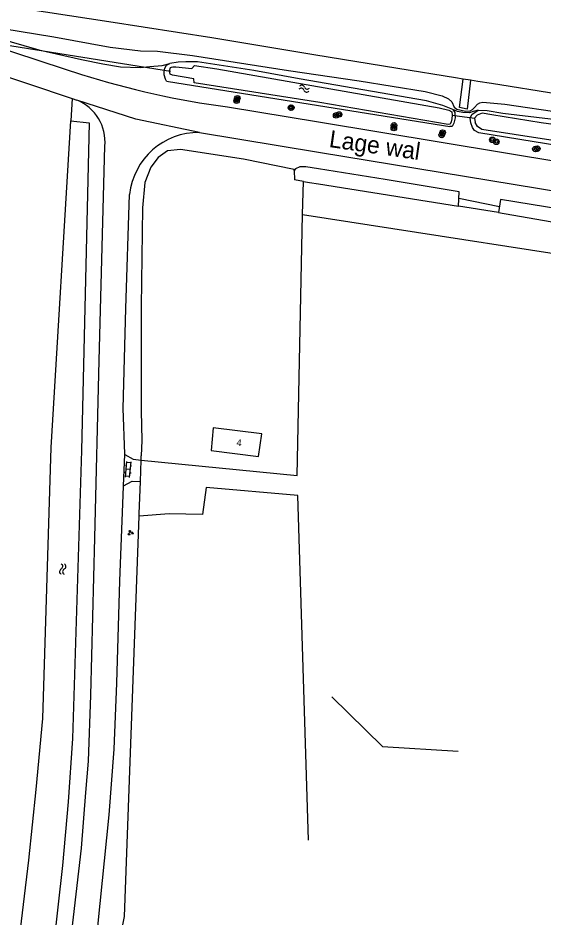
# Model space of a CAD drawing. Extents: x 132994 to 136000, y 393499 to 395512.
# Drawn here: x 133956 to 134032.8, y 394004.5 to 394136.1 of the extents above; entities that cross this region are included whole.
import ezdxf

# ---------------------------------------------------------------- set-up
doc = ezdxf.new("R2010")
doc.units = 0
for name, color, linetype in [('gg-afsc-erfafscheiding', 7, 'Continuous'), ('gg-afsc-hekwerk', 7, 'Continuous'), ('gg-afsc-lijn draadraster', 7, 'Continuous'), ('gg-anno-huisnummerreeks BGT', 7, 'Continuous'), ('gg-anno-openbare ruimte label', 7, 'Continuous'), ('gg-bbg-hoofdgebouw', 7, 'Continuous'), ('gg-knt-BGT kruinlijn', 7, 'Continuous'), ('gg-knt-verharding', 7, 'Continuous'), ('gg-kntw-bovenkant insteek waterloop', 7, 'Continuous'), ('gg-kwrk-duiker nz buis', 7, 'Continuous'), ('gt-grn-groengrens', 7, 'Continuous'), ('gt-grn-vlakafsluiter', 7, 'Continuous'), ('gt-grn-weggrens', 7, 'Continuous'), ('gt-symb-boom', 7, 'Continuous'), ('gt-symb-groenvak', 7, 'Continuous'), ('gt-symb-klinker verharding', 7, 'Continuous'), ('gt-symb-watersymbool', 7, 'Continuous'), ('gx-grn-maaiveld', 7, 'Continuous')]:
    doc.layers.add(name, color=color, linetype=linetype)

# ---------------------------------------------------------------- blocks, each defined once
blk = doc.blocks.new('gt0-BOOM')
at = {"layer": 'gt-symb-boom'}
for radius in [0.4, 0.2]:
    blk.add_circle((0, 0), radius, dxfattribs=at)
blk = doc.blocks.new('gt0-WA')
at = {"layer": 'gt-symb-watersymbool'}
for centre, start, end in [((-0.32, 0.02), 28.0725, 151.9275), ((0.43, 0.42), 208.0725, 331.9275), ((-0.32, -0.43), 28.0725, 151.9275), ((0.43, -0.03), 208.0725, 331.9275)]:
    blk.add_arc(centre, 0.425, start, end, dxfattribs=at)
blk = doc.blocks.new('gt0-GRVAK')
at = {"layer": 'gt-symb-groenvak'}
for p, q in [((-0.11, 0.19), (-0.23, 0.24)), ((-0.18, 0.15), (0.09, 0.15)), ((-0.09, 0.21), (-0.16, 0.32)), ((-0.05, 0.21), (-0.05, 0.39)), ((0, 0.21), (0.06, 0.32)), ((0.01, 0.19), (0.13, 0.24)), ((0.26, -0.05), (0.2, 0.06)), ((0.3, -0.05), (0.3, 0.13)), ((0.35, -0.05), (0.41, 0.06)), ((-0.25, -0.23), (-0.36, -0.18)), ((-0.32, -0.26), (-0.05, -0.26)), ((-0.23, -0.21), (-0.29, -0.1)), ((-0.18, -0.2), (-0.18, -0.02)), ((-0.14, -0.21), (-0.07, -0.1)), ((-0.12, -0.23), (0, -0.18)), ((0.24, -0.07), (0.12, -0.02)), ((0.17, -0.11), (0.44, -0.11)), ((0.37, -0.07), (0.49, -0.02))]:
    blk.add_line(p, q, dxfattribs=at)
blk = doc.blocks.new('gt0-KL1')
at = {"layer": 'gt-symb-klinker verharding'}
for p, q in [((-1.15, 0.3), (1.15, 0.3)), ((-1, -0.3), (-1, 0.3)), ((-0.5, 0.3), (-0.5, 0.45)), ((0, -0.3), (0, 0.3)), ((0.5, 0.3), (0.5, 0.45)), ((1, -0.3), (1, 0.3)), ((-1.15, -0.3), (1.15, -0.3)), ((-0.5, -0.45), (-0.5, -0.3)), ((0.5, -0.45), (0.5, -0.3))]:
    blk.add_line(p, q, dxfattribs=at)

msp = doc.modelspace()

# ---------------------------------------------------------------- linework, layer by layer
at = {"layer": 'gg-afsc-erfafscheiding'}
msp.add_lwpolyline([(133996.44, 394113.81), (133996.44, 394113.96), (133989.01, 394115.45), (133979.8, 394116.87), (133977.88, 394116.7), (133976.53, 394115.71), (133975.45, 394114.28), (133974.6, 394112.07), (133974.24, 394108.35), (133974.06, 394093.94), (133974.05, 394078.67), (133974.13, 394074.31), (133974.06, 394072.08)], dxfattribs=at)
at = {"layer": 'gg-afsc-hekwerk'}
for p, q in [((133973.93, 394068.34), (133974.04, 394071.45)), ((133973.93, 394068.34), (133974.04, 394071.45)), ((133974.04, 394071.45), (133974.06, 394072.08)), ((133974.04, 394071.45), (133974.06, 394072.08)), ((133973.75, 394063.61), (133973.93, 394068.34)), ((133973.75, 394063.61), (133973.93, 394068.34)), ((133973.74, 394063.27), (133973.75, 394063.61)), ((133973.74, 394063.27), (133973.75, 394063.61))]:
    msp.add_line(p, q, dxfattribs=at)
msp.add_lwpolyline([(133970.67, 394000), (133971.62, 394004.71), (133973.74, 394063.27)], dxfattribs=at)
msp.add_lwpolyline([(133970.67, 394000), (133971.62, 394004.71), (133973.74, 394063.27)], dxfattribs=at)
at = {"layer": 'gg-afsc-lijn draadraster'}
for points in [[(133998.53, 394015.87), (133996.94, 394066.28), (133983.57, 394067.44), (133983.03, 394063.53), (133978.15, 394063.63), (133973.74, 394063.27)], [(134001.91, 394036.83), (134009.32, 394029.61), (134020.42, 394028.9)]]:
    msp.add_lwpolyline(points, dxfattribs=at)
at = {"layer": 'gg-bbg-hoofdgebouw'}
msp.add_lwpolyline([(133991.23, 394072), (133991.71, 394075.32), (133984.56, 394076.16), (133984.26, 394072.87), (133991.23, 394072)], dxfattribs=at)
at = {"layer": 'gg-knt-BGT kruinlijn'}
for p, q in [((133953.82, 394134.59), (133961.29, 394133.35)), ((133961.29, 394133.35), (133969.5, 394131.82)), ((133969.5, 394131.82), (133973.95, 394131.29)), ((133973.95, 394131.29), (133976.45, 394131.24)), ((133976.45, 394131.24), (133981.56, 394130.6)), ((133981.56, 394130.6), (133995.6, 394128.41)), ((133995.6, 394128.41), (134005.95, 394126.92)), ((134005.95, 394126.92), (134015.6, 394125.38)), ((134015.6, 394125.38), (134018.07, 394124.72)), ((134018.07, 394124.72), (134018.99, 394124.28)), ((134018.99, 394124.28), (134019.49, 394123.83)), ((134019.49, 394123.83), (134019.84, 394123.09)), ((134019.84, 394123.09), (134020.2, 394122.75)), ((134020.2, 394122.75), (134021.49, 394122.48)), ((134021.49, 394122.48), (134022.16, 394122.54)), ((134022.16, 394122.54), (134022.52, 394122.73)), ((134022.52, 394122.73), (134022.78, 394123)), ((134022.78, 394123), (134023.23, 394123.51)), ((134023.23, 394123.51), (134023.56, 394123.72)), ((134023.56, 394123.72), (134024.02, 394123.8)), ((134024.02, 394123.8), (134027.26, 394123.5)), ((134027.26, 394123.5), (134042.32, 394121.27))]:
    msp.add_line(p, q, dxfattribs=at)
at = {"layer": 'gg-knt-verharding'}
for p, q in [((133962.78, 394128.68), (133965.34, 394127.85)), ((133963.95, 394124.32), (133964.62, 394124.09)), ((133986.65, 394123.12), (134000, 394120.91)), ((133982.6, 394119.37), (134000, 394116.5)), ((134000, 394116.5), (134157.93, 394090.51)), ((133971.45, 394067.72), (133971.64, 394072.3))]:
    msp.add_line(p, q, dxfattribs=at)
for points in [[(133942.63, 394135.11), (133944.19, 394134.74), (133962.78, 394128.68)], [(133944.04, 394130.94), (133944.46, 394130.85), (133963.95, 394124.32)], [(133960.05, 393973.71), (133961.31, 393982.52), (133963.39, 393997.93), (133965.3, 394014.74), (133965.97, 394022.84), (133966.32, 394027.44), (133966.7, 394037.1), (133967.28, 394060.1), (133967.92, 394086.05), (133968.72, 394117.35)], [(133971.64, 394072.3), (133971.64, 394072.36), (133971.43, 394079.02), (133971.8, 394093.64), (133972.33, 394110.3)], [(133971.64, 394072.3), (133972.87, 394071.6), (133974.04, 394071.45)], [(133963.79, 393973.39), (133965.22, 393983.85), (133967.5, 394001.54), (133967.7, 394003.25), (133969.38, 394019.62), (133970.1, 394029.19), (133970.48, 394038.84), (133970.93, 394053.83), (133971.44, 394067.62), (133971.45, 394067.72)], [(133971.45, 394067.72), (133972.71, 394068.38), (133973.93, 394068.34)]]:
    msp.add_lwpolyline(points, dxfattribs=at)
for centre, radius, start, end in [((134002.41, 394244.59), 122.48, 252.3818, 262.6107), ((133962.23, 394118.02), 6.53, 354.1109, 68.5632), ((133982.47, 394109.17), 10.2, 89.2753, 173.6459)]:
    msp.add_arc(centre, radius, start, end, dxfattribs=at)
at = {"layer": 'gg-kntw-bovenkant insteek waterloop'}
for p, q in [((133977.76, 394126.86), (134000, 394123.3)), ((134000, 394123.3), (134019.19, 394120.22)), ((134019.64, 394122.72), (134018.16, 394123.32)), ((133996.44, 394113.81), (133996.45, 394112.42)), ((133998.69, 394112.07), (134000, 394111.86)), ((134000, 394111.86), (134020.44, 394108.6))]:
    msp.add_line(p, q, dxfattribs=at)
for points in [[(133997.15, 394127.22), (133990.51, 394128.42), (133982.28, 394129.69), (133980.6, 394129.69), (133979.47, 394129.65), (133978.23, 394129.46)], [(134018.16, 394123.32), (134015.79, 394124.01), (133997.15, 394127.22)], [(133956.05, 394000), (133957.62, 394012.97), (133958.68, 394023.31), (133959.65, 394033.66), (133960.9, 394073.32), (133963.77, 394121.07)], [(133963.77, 394121.07), (133966.45, 394120.78), (133965.34, 394072.87), (133964, 394030.76), (133963.35, 394021.48), (133962.52, 394012.2), (133961.18, 394000)], [(134000, 394114.05), (133998.15, 394114.32), (133997.26, 394114.34), (133996.63, 394114.06), (133996.44, 394113.81)], [(134020.44, 394108.6), (134020.55, 394110.69), (134009.75, 394112.49), (134000, 394114.05)], [(134057.36, 394102.28), (134057.19, 394104.13), (134056.78, 394104.46), (134055.93, 394104.77), (134026.59, 394109.59), (134026.32, 394107.65)], [(134026.32, 394107.65), (134051.54, 394103.27), (134054.74, 394102.88), (134054.66, 394101.57)]]:
    msp.add_lwpolyline(points, dxfattribs=at)
at = {"layer": 'gg-kwrk-duiker nz buis'}
for p, q in [((134019.54, 394121.91), (134022.82, 394121.45)), ((134020.5, 394109.74), (134026.44, 394108.52))]:
    msp.add_line(p, q, dxfattribs=at)
msp.add_lwpolyline([(133897.87, 394141.41), (133938.59, 394134.68), (133978.32, 394128.35)], dxfattribs=at)
at = {"layer": 'gt-grn-groengrens'}
msp.add_line((133963.95, 394124.32), (133963.77, 394121.07), dxfattribs=at)
at = {"layer": 'gt-grn-vlakafsluiter'}
msp.add_line((134026.32, 394107.65), (134020.44, 394108.6), dxfattribs=at)
at = {"layer": 'gt-grn-weggrens'}
msp.add_lwpolyline([(133982.6, 394119.37), (133973.24, 394121.3), (133964.62, 394124.09)], dxfattribs=at)
at = {"layer": 'gx-grn-maaiveld'}
for p, q in [((134022.24, 394127), (134021.14, 394127.18)), ((134023.36, 394122.65), (134022.6, 394122.43)), ((134000, 394120.91), (134158.62, 394094.62)), ((133997.77, 394112.21), (133996.45, 394112.42)), ((133997.64, 394107.35), (133997.77, 394112.21)), ((133997.77, 394112.21), (133998.69, 394112.07))]:
    msp.add_line(p, q, dxfattribs=at)
for points in [[(134021.14, 394127.18), (134020.04, 394127.35), (134011.61, 394128.7), (133999.3, 394130.71), (133984.38, 394133.18), (133969.33, 394135.55), (133954.31, 394137.81), (133943.34, 394139.62), (133934.23, 394141.04)], [(133943.32, 394135.82), (133947.79, 394134.64), (133952.79, 394133.26), (133959.08, 394131.45), (133965.3, 394130.05), (133968.45, 394129.4), (133971.02, 394128.97), (133973.88, 394128.89), (133975.31, 394129.02), (133977.13, 394129.14), (133978.23, 394129.46)], [(133977.76, 394126.86), (133977.59, 394127.17), (133977.43, 394127.8), (133977.43, 394128.25), (133977.52, 394128.78), (133977.75, 394129.21), (133978.23, 394129.46)], [(133978.17, 394128.39), (133978.35, 394128.86), (133978.48, 394128.9), (133978.7, 394128.98), (133979.13, 394128.98), (133981.46, 394128.73), (133981.84, 394129.18), (133985.09, 394128.68), (134017.65, 394122.97), (134019.07, 394122.61), (134019.49, 394122.36), (134019.54, 394121.91), (134019.49, 394121.38), (134019.41, 394120.94), (134019.24, 394120.58), (134018.93, 394120.54), (134000.19, 394123.76), (133981.82, 394126.62), (133981.73, 394127.23), (133978.64, 394127.74), (133978.28, 394127.88), (133978.17, 394128.39)], [(134022.24, 394127), (134021.71, 394122.77), (134020.59, 394123.01), (134021.14, 394127.18)], [(134192.86, 394099.86), (134190.47, 394100.25), (134180.77, 394101.85), (134167.62, 394103.94), (134152.1, 394106.42), (134129.21, 394110.02), (134117.51, 394111.85), (134104.79, 394113.85), (134090.06, 394116.2), (134078.2, 394118.08), (134035, 394124.96), (134025.3, 394126.51), (134023.31, 394126.83), (134022.24, 394127)], [(134019.64, 394122.72), (134019.93, 394122.28), (134019.97, 394121.5), (134019.78, 394120.72), (134019.51, 394120.26), (134019.19, 394120.22)], [(134022.6, 394122.43), (134022.08, 394122.24), (134021.1, 394122.29), (134020.3, 394122.42), (134019.64, 394122.72)], [(134159.02, 394096.99), (134115.19, 394104.38), (134023.43, 394119.29), (134022.78, 394119.64), (134022.52, 394120.1), (134022.26, 394120.8), (134022.19, 394121.46), (134022.4, 394121.99), (134023.36, 394122.65)], [(134023.36, 394122.65), (134024.63, 394122.59), (134026.96, 394122.19), (134033.94, 394121.35), (134059.48, 394117.21), (134103.96, 394109.86), (134142.92, 394103.92), (134170.09, 394099.44), (134191.93, 394095.98)], [(134206.07, 394093.12), (134200.13, 394093.83), (134183.07, 394096.58), (134159.86, 394100.39), (134142.33, 394103.54), (134124.15, 394106.2), (134079.05, 394113.36), (134051.3, 394117.85), (134039.65, 394119.82), (134032.57, 394120.79), (134025.32, 394121.94), (134023.91, 394122.17), (134023.17, 394121.89), (134022.82, 394121.45), (134022.91, 394120.83)], [(134205.72, 394090.88), (134203.55, 394090.71), (134193.3, 394092.28), (134171.28, 394095.99), (134115.84, 394105.48), (134079.15, 394111.32), (134033.34, 394118.35), (134023.87, 394119.82), (134023.24, 394120.23), (134022.91, 394120.83)], [(133974.04, 394071.45), (133996.86, 394069.19), (133997.64, 394107.35)], [(133997.64, 394107.35), (134051.12, 394099.09), (134052.54, 394068.57), (134053.41, 394032.06), (134054.95, 394016.04), (134056.13, 394016.1)]]:
    msp.add_lwpolyline(points, dxfattribs=at)

# ---------------------------------------------------------------- block references
at = {"layer": 'gt-symb-boom'}
for p in [(133988, 394124), (133988.12, 394124.37), (133995.94, 394122.99), (133996, 394123), (134002.56, 394121.86), (134003, 394122), (134011, 394120), (134011.03, 394120.41), (134018, 394119), (134018.14, 394119.35), (134025.4, 394118.29), (134026, 394118), (134031.7, 394116.95), (134032, 394117)]:
    msp.add_blockref('gt0-BOOM', p, dxfattribs=at)
at = {"layer": 'gt-symb-groenvak'}
msp.add_blockref('gt0-GRVAK', (133972.47, 394060.83), dxfattribs=at)
at = {"layer": 'gt-symb-klinker verharding', "rotation": 84.8937582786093}
msp.add_blockref('gt0-KL1', (133972.16, 394070.1), dxfattribs=at)
at = {"layer": 'gt-symb-watersymbool'}
for p, rotation in [((133997.84, 394125.79), -10.017934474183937), ((133962.56, 394055.48), 88.16532707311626)]:
    msp.add_blockref('gt0-WA', p, dxfattribs=dict(at, rotation=rotation))

# ---------------------------------------------------------------- texts
at = {"layer": 'gg-anno-huisnummerreeks BGT'}
msp.add_text('4', height=1, rotation=354.8, dxfattribs=at).set_placement((133987.95, 394073.55))
at = {"layer": 'gg-anno-openbare ruimte label'}
msp.add_text('Lage wal', height=2.5, rotation=351.8, dxfattribs=at).set_placement((134001.43, 394117.25))

doc.saveas('drawing.dxf')
